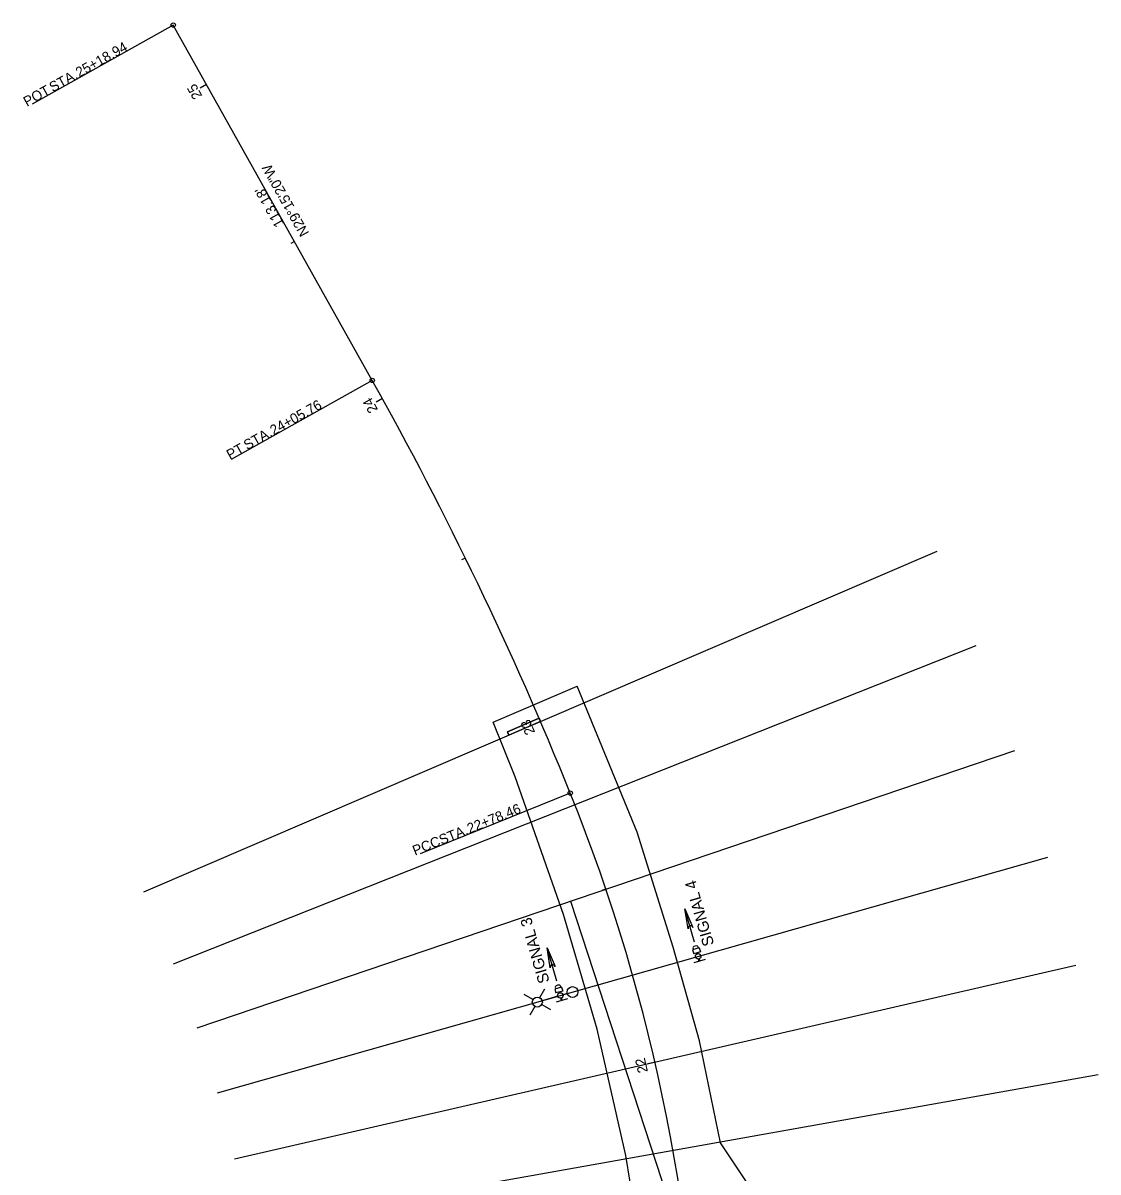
# Model space of a CAD drawing. Extents: x 2283072 to 2287933, y 586198 to 587702.
# Drawn here: x 2284244.8 to 2284543.6, y 587356.1 to 587675.4 of the extents above; entities that cross this region are included whole.
import ezdxf

# ---------------------------------------------------------------- set-up
doc = ezdxf.new("R2010")
doc.units = 0
for name, color, linetype in [('_CIVIL_CONSTRUCTION', 7, 'Continuous'), ('DR_X_Headwall', 7, 'Continuous'), ('DT_X_Void', 7, 'Continuous'), ('PF_X_Ground_Line', 7, 'Continuous'), ('PV_X_EOP', 7, 'Continuous'), ('PV_X_Shoulder_Aggregate', 7, 'Continuous'), ('RS_Raster1', 7, 'Continuous'), ('SV_P_Mon_Cells_Set', 7, 'Continuous'), ('SV_X_Random_Point', 7, 'Continuous'), ('UT_X_Electric_Cells', 7, 'Continuous')]:
    doc.layers.add(name, color=color, linetype=linetype)

msp = doc.modelspace()

# ---------------------------------------------------------------- linework, layer by layer
at = {"layer": '_CIVIL_CONSTRUCTION'}
msp.add_line((2284396.97, 587431.38), (2284441.17, 587296.19), dxfattribs=at)
at = {"layer": 'DR_X_Headwall'}
msp.add_line((2284375.45, 587481.07), (2284398.85, 587491.12), dxfattribs=at)
for points in [[(2284452.62, 587343.14), (2284438.66, 587364.23), (2284432.78, 587392.55), (2284425.53, 587418.61), (2284415.47, 587450.54), (2284398.85, 587491.12)], [(2284419, 587311.53), (2284415.92, 587338.46), (2284412.32, 587360.68), (2284404.38, 587395.77), (2284395.03, 587427.62), (2284381.53, 587465.88), (2284381.59, 587465.9), (2284375.45, 587481.07)]]:
    msp.add_lwpolyline(points, dxfattribs=at)
at = {"layer": 'DT_X_Void'}
for p, q in [((2284278.34, 587433.92), (2284498.87, 587528.63)), ((2284286.62, 587413.97), (2284509.74, 587502.39)), ((2284293.16, 587396.18), (2284520.44, 587473.26)), ((2284298.79, 587378.08), (2284529.67, 587443.62)), ((2284303.51, 587359.72), (2284537.39, 587413.56)), ((2284307.29, 587341.14), (2284543.59, 587383.15))]:
    msp.add_line(p, q, dxfattribs=at)
at = {"layer": 'PF_X_Ground_Line'}
for p, q in [((2284431.43, 587420), (2284428.73, 587429.27)), ((2284429.63, 587423.68), (2284428.73, 587429.27)), ((2284428.73, 587429.27), (2284430.98, 587424.07)), ((2284393.13, 587409.13), (2284390.44, 587418.4)), ((2284391.33, 587412.8), (2284390.44, 587418.4)), ((2284390.44, 587418.4), (2284392.68, 587413.19)), ((2284432.76, 587418.36), (2284430.9, 587417.82)), ((2284430.9, 587417.82), (2284431.22, 587416.72)), ((2284431, 587418.36), (2284431.14, 587417.9)), ((2284431, 587418.36), (2284431.14, 587417.9)), ((2284433.08, 587417.26), (2284431.22, 587416.72)), ((2284432.11, 587416.7), (2284432.04, 587416.96)), ((2284432.11, 587416.7), (2284432.04, 587416.96)), ((2284432.34, 587416.77), (2284432.27, 587417.02)), ((2284432.34, 587416.77), (2284432.27, 587417.02)), ((2284432.38, 587418.76), (2284432.52, 587418.3)), ((2284432.38, 587418.76), (2284432.52, 587418.3)), ((2284432.76, 587418.36), (2284433.08, 587417.26)), ((2284434.39, 587415.12), (2284431.28, 587414.21)), ((2284432.72, 587414.63), (2284432.53, 587415.27)), ((2284432.72, 587414.63), (2284432.53, 587415.27)), ((2284432.95, 587414.7), (2284432.76, 587415.34)), ((2284432.95, 587414.7), (2284432.76, 587415.34)), ((2284388.42, 587404.55), (2284389.79, 587407)), ((2284394.46, 587407.49), (2284392.6, 587406.95)), ((2284392.6, 587406.95), (2284392.92, 587405.85)), ((2284392.7, 587407.49), (2284392.84, 587407.02)), ((2284392.7, 587407.49), (2284392.84, 587407.02)), ((2284394.09, 587407.89), (2284394.22, 587407.43)), ((2284394.09, 587407.89), (2284394.22, 587407.43)), ((2284394.46, 587407.49), (2284394.78, 587406.39)), ((2284386.52, 587404.02), (2284384.07, 587405.38)), ((2284393.41, 587404.94), (2284389.08, 587403.71)), ((2284394.78, 587406.39), (2284392.92, 587405.85)), ((2284396.09, 587404.25), (2284392.98, 587403.34)), ((2284393.81, 587405.83), (2284393.74, 587406.08)), ((2284393.81, 587405.83), (2284393.74, 587406.08)), ((2284394.04, 587405.9), (2284393.97, 587406.15)), ((2284394.04, 587405.9), (2284393.97, 587406.15)), ((2284394.42, 587403.76), (2284394.23, 587404.4)), ((2284394.42, 587403.76), (2284394.23, 587404.4)), ((2284394.65, 587403.83), (2284394.46, 587404.46)), ((2284394.65, 587403.83), (2284394.46, 587404.46)), ((2284396.07, 587405.7), (2284394.86, 587405.36)), ((2284387.06, 587402.11), (2284385.69, 587399.66)), ((2284388.96, 587402.65), (2284391.41, 587401.28))]:
    msp.add_line(p, q, dxfattribs=at)
for centre, radius in [((2284432.44, 587416.02), 0.757), ((2284397.52, 587406.11), 1.5), ((2284387.74, 587403.33), 1.4), ((2284394.14, 587405.15), 0.757)]:
    msp.add_circle(centre, radius, dxfattribs=at)
for centre in [(2284430.3, 587423.87), (2284392, 587413)]:
    msp.add_arc(centre, 0.702, 16.1869, 196.1869, dxfattribs=at)
for centre in [(2284431.69, 587418.56), (2284431.69, 587418.56), (2284393.39, 587407.69), (2284393.39, 587407.69)]:
    msp.add_ellipse(centre, major_axis=(0.692, 0.202), ratio=0.45371, start_param=0, end_param=3.141593, dxfattribs=at)
at = {"layer": 'PV_X_EOP'}
for p, q in [((2284286.54, 587674.83), (2284247.28, 587652.83)), ((2284341.85, 587576.08), (2284302.59, 587554.09)), ((2284396.89, 587461.39), (2284355.17, 587444.52))]:
    msp.add_line(p, q, dxfattribs=at)
for centre in [(2284286.54, 587674.83), (2284341.85, 587576.08), (2284396.89, 587461.39)]:
    msp.add_circle(centre, 0.6, dxfattribs=at)
at = {"layer": 'RS_Raster1'}
for p, q in [((2284295.79, 587658.31), (2284294.05, 587657.33)), ((2284320.23, 587614.68), (2284319.18, 587614.1)), ((2284344.65, 587571.05), (2284342.9, 587570.08)), ((2284367.74, 587526.71), (2284366.66, 587526.18)), ((2284388.6, 587481.28), (2284386.77, 587480.49)), ((2284406.8, 587434.72), (2284405.66, 587434.33)), ((2284420.45, 587386.64), (2284418.5, 587386.19))]:
    msp.add_line(p, q, dxfattribs=at)
at = {"layer": 'SV_X_Random_Point'}
msp.add_line((2284341.85, 587576.08), (2284286.54, 587674.83), dxfattribs=at)
msp.add_line((2284341.85, 587576.08), (2284286.54, 587674.83), dxfattribs=at)
for centre, radius, start, end in [((2283462.79, 587083.67), 1007.58, 22.01669, 29.25551), ((2283462.79, 587083.67), 1007.58, 22.01669, 29.25551), ((2283936.53, 587275.24), 496.57, 0.3751, 22.0167), ((2283936.53, 587275.24), 496.57, 0.3751, 22.0167)]:
    msp.add_arc(centre, radius, start, end, dxfattribs=at)
at = {"layer": 'UT_X_Electric_Cells'}
for p, q in [((2284388.21, 587482.19), (2284379.4, 587478.41)), ((2284388.6, 587481.28), (2284379.78, 587477.48)), ((2284388.21, 587482.19), (2284388.6, 587481.28)), ((2284379.4, 587478.41), (2284379.78, 587477.48))]:
    msp.add_line(p, q, dxfattribs=at)
msp.add_lwpolyline([(2284388.6, 587481.28), (2284379.78, 587477.48), (2284379.4, 587478.41), (2284388.21, 587482.19)], dxfattribs=at)
msp.add_arc((2283462.79, 587083.67), 1007.58, 23.24175, 23.29862, dxfattribs=at)

# ---------------------------------------------------------------- texts
at = {"layer": 'PF_X_Ground_Line'}
for s, p in [('SIGNAL 4', (2284436.92, 587419.37)), ('SIGNAL 3', (2284391.17, 587409.03))]:
    msp.add_text(s, height=3.125, rotation=106.1869, dxfattribs=at).set_placement(p)
at = {"layer": 'PV_X_EOP'}
for s, rotation, p in [('25+18.94', 29.2555, (2284260.39, 587660.22)), (' STA. ', 29.2555, (2284252.14, 587655.6)), ('POT', 29.2555, (2284245.86, 587652.09)), ('24+05.76', 29.2555, (2284314.41, 587560.76)), (' STA. ', 29.2555, (2284306.16, 587556.14)), ('PT', 29.2555, (2284302.31, 587553.98)), ('22+78.46', 22.0167, (2284368.88, 587450.11)), (' STA. ', 22.0167, (2284360.12, 587446.57)), ('PCC', 22.0167, (2284353.73, 587443.98))]:
    msp.add_text(s, height=2.8, rotation=rotation, dxfattribs=at).set_placement(p)
at = {"layer": 'PV_X_Shoulder_Aggregate'}
msp.add_text('N29°15\'20"W', height=2.8, rotation=119.2555, dxfattribs=at).set_placement((2284324.4, 587617.06))
at = {"layer": 'RS_Raster1'}
for s, rotation, p in [('25', 119.2555, (2284294.68, 587655.18)), ('24', 118.9282, (2284343.51, 587567.96)), ('23', 113.2418, (2284387.16, 587478.31)), ('22', 102.9641, (2284418.5, 587383.97))]:
    msp.add_text(s, height=2.8, rotation=rotation, dxfattribs=at).set_placement(p)
at = {"layer": 'SV_P_Mon_Cells_Set'}
msp.add_text("113.18'", height=2.8, rotation=119.2555, dxfattribs=at).set_placement((2284317.42, 587619.61))

doc.saveas('drawing.dxf')
